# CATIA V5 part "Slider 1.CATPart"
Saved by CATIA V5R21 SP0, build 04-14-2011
Part number: Part 2
Bounding box of the stored display mesh (mm): x 0 to 20, y -5 to 5, z -5 to 5
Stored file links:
  D:\CATIA V5R21 E-RESOURCES\CATIA-V5R21\catia-v5r21-prt\c16-catia-v5r20-prt\Cable Joint - (Fig16-60)\CAT_V5R21_Slider 1.CATPart
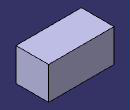
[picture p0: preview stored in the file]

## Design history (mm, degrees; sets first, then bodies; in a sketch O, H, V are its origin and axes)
Body1 (main body)
  Sketch1 on yz-plane, origin (0, 0, 0), H (0, 1, 0), V (0, 0, 1)
    line L1 (5, 5) -> (5, -5)
    line L2 (5, -5) -> (-5, -5)
    line L3 (-5, -5) -> (-5, 5)
    line L4 (-5, 5) -> (5, 5)
    length L4 = 10
    length L1 = 10
    vertical: L1 V, L3 V
    horizontal: L2 H, L4 H
    equidistance: L1 L3 O, L2 L4 O
  Pad1: profile Sketch1, direction (1, 0, 0), length 20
